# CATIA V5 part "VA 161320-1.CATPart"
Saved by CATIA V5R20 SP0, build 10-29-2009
Part number: VA 161320-1
Revision: ANY
Definition: UNKNOWN
Nomenclature: VA 161320-1
Source: Unknown
Bounding box of the stored display mesh (mm): x -6.455 to 6.455, y 0 to 15.5, z -6.293 to 6.293
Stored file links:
  C:\Users\Utente\Desktop\IO LAVORO\3D X SITO CF\CUMSA\3D files VA\VA 161320\VA 161320-1.CATPart
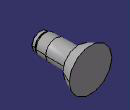
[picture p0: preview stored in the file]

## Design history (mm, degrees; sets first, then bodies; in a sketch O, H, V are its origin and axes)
Body1 "Revolución1" (main body)
  Solid1: solid without history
